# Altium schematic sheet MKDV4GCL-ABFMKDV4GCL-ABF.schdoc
size 127 x 101 mm
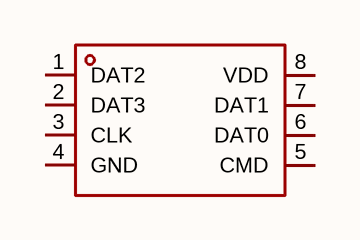
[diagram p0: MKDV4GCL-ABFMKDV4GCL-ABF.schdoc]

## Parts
U?  mkdv4gcl-abf  [LGA-8_L8.0-W6.0-P1.27-TL_MKDV4GCL-ABF]  (value not drawn)

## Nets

Not connected (* = marked no-connect by the designer): U? 1(DAT2) 2(DAT3) 3(CLK) 4(GND) 5(CMD) 6(DAT0) 7(DAT1) 8(VDD)

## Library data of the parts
U? = mkdv4gcl-abf: 存储容量:4Gbit;时钟频率(fc):50MHz;工作电压:2.7V~3.6V;; Manufacturer: MK(米客方德); AddInBom: yes; ModelId: ef50f8f4e0d745e797621e4f42c5cff2; ModelTransform: 314.96,236.22,0,0,0,0,0,0,0; Memory Size: 4Gbit; Interface: SD接口; Clock Frequency: 50MHz; Data Retention - TDR (Year): 10年; Standby Supply Current: 80uA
